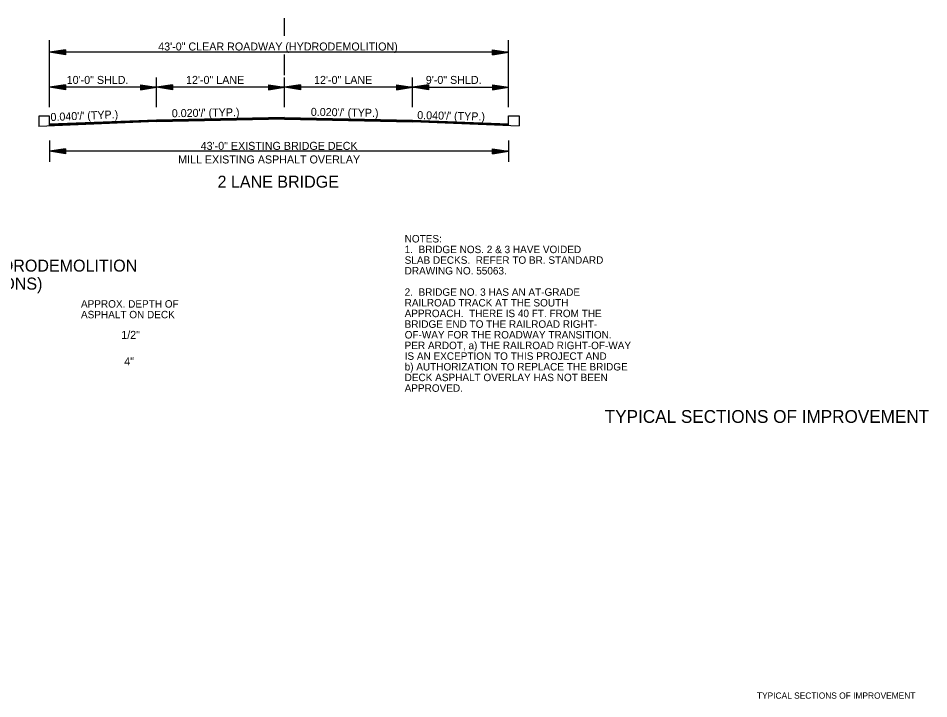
# Model space of a CAD drawing. Extents: x 549600 to 1930787, y -1955432 to 596640.
# Drawn here: x 551693 to 552546, y -1945691 to -1945053 of the extents above; entities that cross this region are included whole.
import ezdxf

# ---------------------------------------------------------------- set-up
doc = ezdxf.new("R2010")
doc.units = 0
for name, color, linetype in [('R_Border', 7, 'Continuous'), ('R_Border Notes', 7, 'Continuous'), ('R_Border Prem', 7, 'Continuous'), ('S_AREA_CALC', 7, 'Continuous')]:
    doc.layers.add(name, color=color, linetype=linetype)

msp = doc.modelspace()

# ---------------------------------------------------------------- linework, layer by layer
at = {"layer": 'R_Border'}
for p, q in [((551711.85, -1945144.67), (551711.84, -1945154.18)), ((551722.02, -1945144.67), (551711.85, -1945144.67)), ((551722.02, -1945153.47), (551722.02, -1945144.67)), ((552152.02, -1945153.07), (552152.02, -1945144.27)), ((552152.02, -1945144.27), (552162.18, -1945144.27)), ((552162.18, -1945144.27), (552162.2, -1945153.78))]:
    msp.add_line(p, q, dxfattribs=at)
at = {"layer": 'S_AREA_CALC'}
for p, q in [((551942.02, -1945069.42), (551942.02, -1945052.79)), ((551722.02, -1945136.32), (551722.02, -1945073.3)), ((552152.02, -1945136.32), (552152.02, -1945073.3)), ((551737.02, -1945082.48), (551722.02, -1945084.73)), ((552152.02, -1945084.73), (551722.02, -1945084.73)), ((551737.02, -1945086.98), (551722.02, -1945084.73)), ((551737.02, -1945082.85), (551724.52, -1945084.73)), ((551737.02, -1945086.6), (551724.52, -1945084.73)), ((551737.02, -1945083.23), (551727.1, -1945084.73)), ((551737.02, -1945086.22), (551727.1, -1945084.73)), ((551737.02, -1945083.61), (551729.6, -1945084.73)), ((551737.02, -1945085.84), (551729.6, -1945084.73)), ((551737.02, -1945084), (551732.14, -1945084.73)), ((551737.02, -1945085.46), (551732.14, -1945084.73)), ((551737.02, -1945084.37), (551734.65, -1945084.73)), ((551737.02, -1945085.08), (551734.65, -1945084.73)), ((551737.02, -1945082.48), (551737.02, -1945086.98)), ((552137.02, -1945082.48), (552152.02, -1945084.73)), ((552137.02, -1945086.98), (552137.02, -1945082.48)), ((552137.02, -1945082.85), (552149.51, -1945084.73)), ((552137.02, -1945083.23), (552146.93, -1945084.73)), ((552137.02, -1945083.61), (552144.44, -1945084.73)), ((552137.02, -1945083.99), (552141.89, -1945084.73)), ((552137.02, -1945084.37), (552139.39, -1945084.73)), ((552137.02, -1945086.98), (552152.02, -1945084.73)), ((552137.02, -1945085.45), (552141.89, -1945084.73)), ((552137.02, -1945086.22), (552146.93, -1945084.73)), ((552137.02, -1945086.6), (552149.51, -1945084.73)), ((552137.02, -1945085.84), (552144.44, -1945084.73)), ((552137.02, -1945085.08), (552139.39, -1945084.73)), ((551942.02, -1945098.26), (551942.02, -1945086.81)), ((551942.02, -1945106.25), (551942.02, -1945098.26)), ((551822.02, -1945136.32), (551822.02, -1945108.37)), ((551942.02, -1945136.32), (551942.02, -1945108.37)), ((552062.02, -1945136.32), (552062.02, -1945108.37)), ((551737.02, -1945115.31), (551722.02, -1945117.56)), ((551822.02, -1945117.56), (551722.02, -1945117.56)), ((551737.02, -1945119.81), (551722.02, -1945117.56)), ((551737.02, -1945115.69), (551724.52, -1945117.56)), ((551737.02, -1945119.44), (551724.52, -1945117.56)), ((551737.02, -1945116.07), (551727.1, -1945117.56)), ((551737.02, -1945119.05), (551727.1, -1945117.56)), ((551737.02, -1945116.44), (551729.6, -1945117.56)), ((551737.02, -1945118.68), (551729.6, -1945117.56)), ((551737.02, -1945116.83), (551732.14, -1945117.56)), ((551737.02, -1945118.3), (551732.14, -1945117.56)), ((551737.02, -1945117.21), (551734.65, -1945117.56)), ((551737.02, -1945117.91), (551734.65, -1945117.56)), ((551737.02, -1945115.31), (551737.02, -1945119.81)), ((551807.02, -1945115.31), (551822.02, -1945117.56)), ((551807.02, -1945115.31), (551807.02, -1945119.81)), ((551807.02, -1945115.69), (551819.51, -1945117.56)), ((551807.02, -1945116.07), (551816.93, -1945117.56)), ((551807.02, -1945116.44), (551814.44, -1945117.56)), ((551807.02, -1945116.83), (551811.89, -1945117.56)), ((551807.02, -1945117.21), (551809.39, -1945117.56)), ((551807.02, -1945119.81), (551822.02, -1945117.56)), ((551807.02, -1945118.3), (551811.89, -1945117.56)), ((551807.02, -1945119.05), (551816.93, -1945117.56)), ((551807.02, -1945119.44), (551819.51, -1945117.56)), ((551807.02, -1945118.68), (551814.44, -1945117.56)), ((551807.02, -1945117.91), (551809.39, -1945117.56)), ((551837.02, -1945115.31), (551822.02, -1945117.56)), ((551942.02, -1945117.56), (551822.02, -1945117.56)), ((551837.02, -1945119.81), (551822.02, -1945117.56)), ((551837.02, -1945115.69), (551824.52, -1945117.56)), ((551837.02, -1945119.44), (551824.52, -1945117.56)), ((551837.02, -1945116.07), (551827.1, -1945117.56)), ((551837.02, -1945119.05), (551827.1, -1945117.56)), ((551837.02, -1945116.44), (551829.6, -1945117.56)), ((551837.02, -1945118.68), (551829.6, -1945117.56)), ((551837.02, -1945116.83), (551832.14, -1945117.56)), ((551837.02, -1945118.3), (551832.14, -1945117.56)), ((551837.02, -1945117.21), (551834.65, -1945117.56)), ((551837.02, -1945117.91), (551834.65, -1945117.56)), ((551837.02, -1945115.31), (551837.02, -1945119.81)), ((551927.02, -1945115.31), (551942.02, -1945117.56)), ((551927.02, -1945115.31), (551927.02, -1945119.81)), ((551927.02, -1945115.69), (551939.51, -1945117.56)), ((551927.02, -1945116.07), (551936.93, -1945117.56)), ((551927.02, -1945116.44), (551934.44, -1945117.56)), ((551927.02, -1945116.83), (551931.89, -1945117.56)), ((551927.02, -1945117.21), (551929.39, -1945117.56)), ((551927.02, -1945119.81), (551942.02, -1945117.56)), ((551927.02, -1945118.3), (551931.89, -1945117.56)), ((551927.02, -1945119.05), (551936.93, -1945117.56)), ((551927.02, -1945119.44), (551939.51, -1945117.56)), ((551927.02, -1945118.68), (551934.44, -1945117.56)), ((551927.02, -1945117.91), (551929.39, -1945117.56)), ((551957.02, -1945115.31), (551942.02, -1945117.56)), ((552062.02, -1945117.56), (551942.02, -1945117.56)), ((551957.02, -1945119.81), (551942.02, -1945117.56)), ((551957.02, -1945115.69), (551944.52, -1945117.56)), ((551957.02, -1945119.44), (551944.52, -1945117.56)), ((551957.02, -1945116.07), (551947.1, -1945117.56)), ((551957.02, -1945119.05), (551947.1, -1945117.56)), ((551957.02, -1945116.44), (551949.6, -1945117.56)), ((551957.02, -1945118.68), (551949.6, -1945117.56)), ((551957.02, -1945116.83), (551952.14, -1945117.56)), ((551957.02, -1945118.3), (551952.14, -1945117.56)), ((551957.02, -1945117.21), (551954.65, -1945117.56)), ((551957.02, -1945117.91), (551954.65, -1945117.56)), ((551957.02, -1945115.31), (551957.02, -1945119.81)), ((552047.02, -1945115.31), (552062.02, -1945117.56)), ((552047.02, -1945115.31), (552047.02, -1945119.81)), ((552047.02, -1945115.69), (552059.51, -1945117.56)), ((552047.02, -1945116.07), (552056.93, -1945117.56)), ((552047.02, -1945116.44), (552054.44, -1945117.56)), ((552047.02, -1945116.83), (552051.89, -1945117.56)), ((552047.02, -1945117.21), (552049.39, -1945117.56)), ((552047.02, -1945119.81), (552062.02, -1945117.56)), ((552047.02, -1945118.3), (552051.89, -1945117.56)), ((552047.02, -1945119.05), (552056.93, -1945117.56)), ((552047.02, -1945119.44), (552059.51, -1945117.56)), ((552047.02, -1945118.68), (552054.44, -1945117.56)), ((552047.02, -1945117.91), (552049.39, -1945117.56)), ((552077.02, -1945115.31), (552062.02, -1945117.56)), ((552062.02, -1945117.56), (552152.02, -1945117.56)), ((552077.02, -1945119.81), (552062.02, -1945117.56)), ((552077.02, -1945115.69), (552064.52, -1945117.56)), ((552077.02, -1945119.44), (552064.52, -1945117.56)), ((552077.02, -1945116.07), (552067.1, -1945117.56)), ((552077.02, -1945119.05), (552067.1, -1945117.56)), ((552077.02, -1945116.44), (552069.6, -1945117.56)), ((552077.02, -1945118.68), (552069.6, -1945117.56)), ((552077.02, -1945116.83), (552072.14, -1945117.56)), ((552077.02, -1945118.3), (552072.14, -1945117.56)), ((552077.02, -1945117.21), (552074.65, -1945117.56)), ((552077.02, -1945117.91), (552074.65, -1945117.56)), ((552077.02, -1945115.31), (552077.02, -1945119.81)), ((552137.02, -1945115.31), (552152.02, -1945117.56)), ((552137.02, -1945115.31), (552137.02, -1945119.81)), ((552137.02, -1945115.69), (552149.51, -1945117.56)), ((552137.02, -1945116.07), (552146.93, -1945117.56)), ((552137.02, -1945116.44), (552144.44, -1945117.56)), ((552137.02, -1945116.83), (552141.89, -1945117.56)), ((552137.02, -1945117.21), (552139.39, -1945117.56)), ((552137.02, -1945119.81), (552152.02, -1945117.56)), ((552137.02, -1945118.3), (552141.89, -1945117.56)), ((552137.02, -1945119.05), (552146.93, -1945117.56)), ((552137.02, -1945119.44), (552149.51, -1945117.56)), ((552137.02, -1945118.68), (552144.44, -1945117.56)), ((552137.02, -1945117.91), (552139.39, -1945117.56)), ((551822.02, -1945149.77), (551711.84, -1945154.18)), ((551822.02, -1945148.27), (551722.02, -1945152.27)), ((551822.02, -1945148.57), (551722.02, -1945152.57)), ((551822.02, -1945148.87), (551722.02, -1945152.87)), ((551822.02, -1945149.17), (551722.02, -1945153.17)), ((551822.02, -1945149.47), (551722.02, -1945153.47)), ((551942.02, -1945145.87), (551822.02, -1945148.27)), ((551942.02, -1945146.17), (551822.02, -1945148.57)), ((551942.02, -1945146.47), (551822.02, -1945148.87)), ((551942.02, -1945146.77), (551822.02, -1945149.17)), ((551942.02, -1945147.07), (551822.02, -1945149.47)), ((551942.02, -1945147.37), (551822.02, -1945149.77)), ((551942.02, -1945147.54), (551822.02, -1945149.94)), ((551942.02, -1945145.87), (552062.02, -1945148.27)), ((551942.02, -1945146.17), (552062.02, -1945148.57)), ((551942.02, -1945146.47), (552062.02, -1945148.87)), ((551942.02, -1945146.77), (552062.02, -1945149.17)), ((551942.02, -1945147.07), (552062.02, -1945149.47)), ((551942.02, -1945147.37), (552062.02, -1945149.77)), ((551942.02, -1945147.54), (552062.02, -1945149.94)), ((552062.02, -1945148.27), (552152.02, -1945151.87)), ((552062.02, -1945148.57), (552152.02, -1945152.17)), ((552062.02, -1945148.87), (552152.02, -1945152.47)), ((552062.02, -1945149.17), (552152.02, -1945152.77)), ((552062.02, -1945149.47), (552152.02, -1945153.07)), ((552062.02, -1945149.77), (552162.2, -1945153.78)), ((551722.02, -1945167.53), (551722.02, -1945187.53)), ((552152.02, -1945167.28), (552152.02, -1945187.28)), ((551737.02, -1945175.28), (551722.02, -1945177.53)), ((551737.02, -1945179.78), (551722.02, -1945177.53)), ((552152.02, -1945177.53), (551722.02, -1945177.53)), ((551737.02, -1945175.65), (551724.52, -1945177.53)), ((551737.02, -1945179.4), (551724.52, -1945177.53)), ((551737.02, -1945176.04), (551727.1, -1945177.53)), ((551737.02, -1945179.02), (551727.1, -1945177.53)), ((551737.02, -1945176.41), (551729.6, -1945177.53)), ((551737.02, -1945178.65), (551729.6, -1945177.53)), ((551737.02, -1945176.8), (551732.14, -1945177.53)), ((551737.02, -1945178.26), (551732.14, -1945177.53)), ((551737.02, -1945177.18), (551734.65, -1945177.53)), ((551737.02, -1945177.88), (551734.65, -1945177.53)), ((551737.02, -1945175.28), (551737.02, -1945179.78)), ((552137.02, -1945175.28), (552152.02, -1945177.53)), ((552137.02, -1945179.78), (552137.02, -1945175.28)), ((552137.02, -1945175.65), (552149.51, -1945177.53)), ((552137.02, -1945176.04), (552146.93, -1945177.53)), ((552137.02, -1945176.41), (552144.44, -1945177.53)), ((552137.02, -1945176.79), (552141.89, -1945177.53)), ((552137.02, -1945177.18), (552139.39, -1945177.53)), ((552137.02, -1945179.78), (552152.02, -1945177.53)), ((552137.02, -1945178.26), (552141.89, -1945177.53)), ((552137.02, -1945179.02), (552146.93, -1945177.53)), ((552137.02, -1945179.4), (552149.51, -1945177.53)), ((552137.02, -1945178.65), (552144.44, -1945177.53)), ((552137.02, -1945177.88), (552139.39, -1945177.53))]:
    msp.add_line(p, q, dxfattribs=at)

# ---------------------------------------------------------------- texts
at = {"layer": 'R_Border'}
for s, p in [('1/2"', (551789.14, -1945353.39)), ('4"', (551791.91, -1945378.31))]:
    msp.add_text(s, height=7.5, dxfattribs=at).set_placement(p)
msp.add_text('TYPICAL SECTIONS OF IMPROVEMENT', height=12, rotation=360, dxfattribs=at).set_placement((552242.27, -1945432.14))
at = {"layer": 'R_Border Notes'}
for s, p in [('NOTES: ', (552054.73, -1945263.03)), ('1.  BRIDGE NOS. 2 & 3 HAVE VOIDED', (552054.73, -1945273.03)), ('SLAB DECKS.  REFER TO BR. STANDARD', (552054.73, -1945283.03)), ('DRAWING NO. 55063.', (552054.73, -1945293.03)), ('2.  BRIDGE NO. 3 HAS AN AT-GRADE  ', (552054.73, -1945313.03)), ('APPROX. DEPTH OF', (551751.39, -1945324.12)), ('RAILROAD TRACK AT THE SOUTH', (552054.73, -1945323.03)), ('ASPHALT ON DECK', (551751.39, -1945334.12)), ('APPROACH.  THERE IS 40 FT. FROM THE', (552054.73, -1945333.03)), ('BRIDGE END TO THE RAILROAD RIGHT-', (552054.73, -1945343.03)), ('OF-WAY FOR THE ROADWAY TRANSITION. ', (552054.73, -1945353.03)), ('PER ARDOT, a) THE RAILROAD RIGHT-OF-WAY', (552054.73, -1945363.03)), ('IS AN EXCEPTION TO THIS PROJECT AND', (552054.73, -1945373.03)), ('b) AUTHORIZATION TO REPLACE THE BRIDGE ', (552054.73, -1945383.03)), ('DECK ASPHALT OVERLAY HAS NOT BEEN', (552054.73, -1945393.03)), ('APPROVED. ', (552054.73, -1945403.03))]:
    msp.add_text(s, height=7, dxfattribs=at).set_placement(p)
at = {"layer": 'R_Border Prem'}
msp.add_text('TYPICAL SECTIONS OF IMPROVEMENT', height=5.862, rotation=360, dxfattribs=at).set_placement((552384.89, -1945690.73))
at = {"layer": 'S_AREA_CALC'}
for s, height, p in [('43\'-0" CLEAR ROADWAY (HYDRODEMOLITION)', 7.5, (551823.77, -1945083.06)), ('10\'-0" SHLD.', 7.5, (551738, -1945114.39)), ('12\'-0" LANE', 7.5, (551849.83, -1945114.39)), ('12\'-0" LANE', 7.5, (551969.83, -1945114.39)), ('9\'-0" SHLD.', 7.5, (552074.54, -1945114.39)), ('43\'-0" EXISTING BRIDGE DECK', 7.5, (551863.57, -1945176.21)), ('MILL EXISTING ASPHALT OVERLAY', 7.5, (551842.44, -1945188.97)), ('2 LANE BRIDGE', 11.25, (551879.39, -1945211.67)), ('43 FT. CLEAR ROADWAY BRIDGE - HYDRODEMOLITION', 11.25, (551401.23, -1945290.35)), ('(ROADWAY TRANSITIONS)', 11.25, (551522.18, -1945307.22))]:
    msp.add_text(s, height=height, dxfattribs=at).set_placement(p)
for s, rotation, p in [("  0.040'/' (TYP.)", 2.44797, (551717.39, -1945149.47)), ("0.020'/' (TYP.)", 0.97192, (551836.54, -1945145.67)), ("0.020'/' (TYP.)", 359.02808, (551966.72, -1945144.29)), ("0.040'/' (TYP.)", 358.68162, (552066.46, -1945147.3))]:
    msp.add_text(s, height=7.5, rotation=rotation, dxfattribs=at).set_placement(p)

doc.saveas('drawing.dxf')
